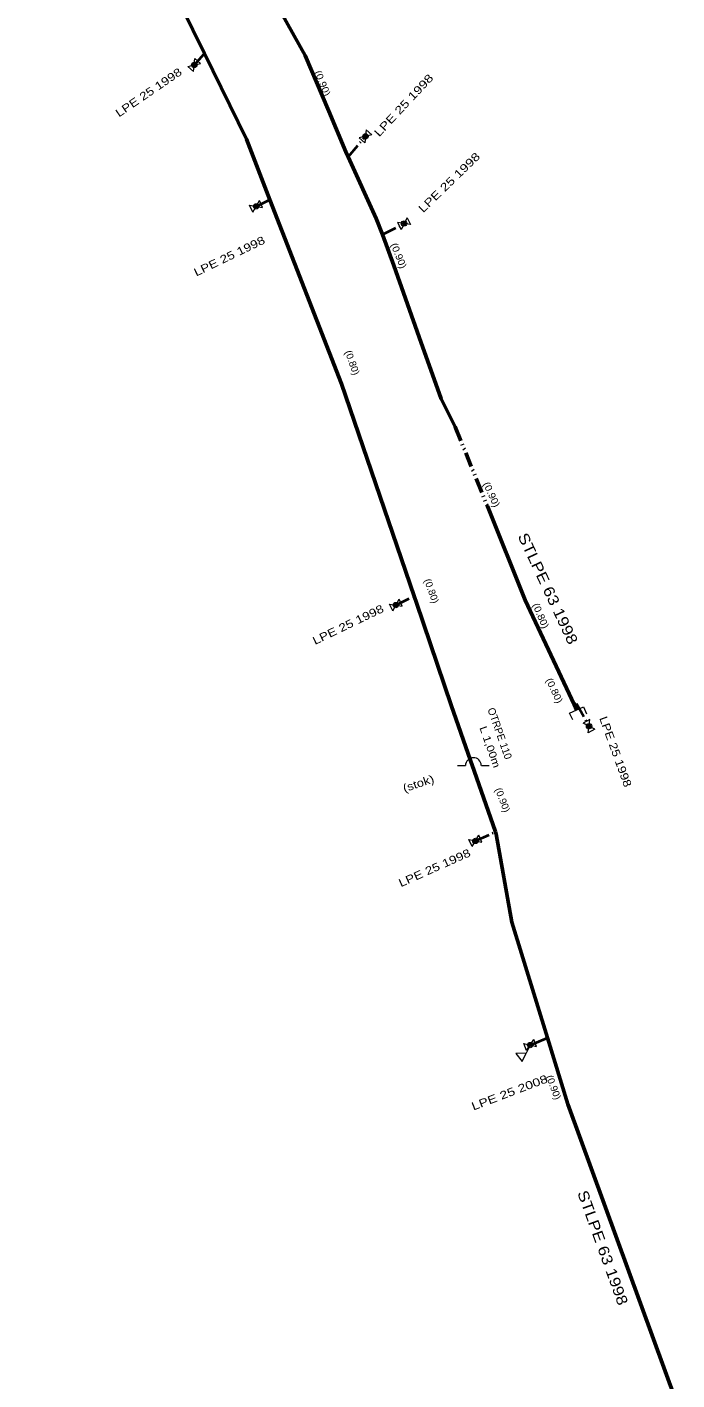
# Model space of a CAD drawing. Extents: x -648036 to -642998, y -1161549 to -1158141.
# Drawn here: x -646480.8 to -646420, y -1161219.3 to -1161092.5 of the extents above; entities that cross this region are included whole.
import ezdxf
from ezdxf.enums import TextEntityAlignment as Align

# ---------------------------------------------------------------- set-up
doc = ezdxf.new("R2010")
doc.units = 0
doc.header["$LTSCALE"] = 0.28
doc.linetypes.add('DASH_DOUBLE_DOT', pattern=[9.2, 5, -1.2, 0.3, -1.2, 0.3, -1.2])
for name, color, linetype, lineweight in [('12', 7, 'DASH_DOUBLE_DOT', 40), ('14', 7, 'Continuous', 13), ('15', 7, 'Continuous', 13), ('19', 7, 'Continuous', 13), ('8', 7, 'Continuous', 53)]:
    doc.layers.add(name, color=color, linetype=linetype, lineweight=lineweight)
for name, color, linetype in [('20', 7, 'Continuous'), ('22', 7, 'Continuous'), ('24', 7, 'Continuous'), ('27', 7, 'Continuous'), ('28', 7, 'Continuous')]:
    doc.layers.add(name, color=color, linetype=linetype)

msp = doc.modelspace()

# ---------------------------------------------------------------- linework, layer by layer
at = {"layer": '12'}
for p, q in [((-646465.2, -1161096.1), (-646464.24, -1161095.03)), ((-646450.79, -1161104.69), (-646449.16, -1161102.78)), ((-646459.4, -1161109.34), (-646458.11, -1161108.72)), ((-646447.58, -1161111.99), (-646445.55, -1161110.95)), ((-646446.32, -1161146.71), (-646444.6, -1161145.87)), ((-646438.87, -1161168.81), (-646436.99, -1161167.96))]:
    msp.add_line(p, q, dxfattribs=at)
at = {"layer": '12', "linetype": 'Continuous'}
msp.add_line((-646433.744, -1161187.942), (-646432.114, -1161187.278), dxfattribs=at)
at = {"layer": '12'}
msp.add_lwpolyline([(-646429.63, -1161156.03), (-646429.4, -1161155.93), (-646428.23, -1161158.06)], dxfattribs=at)
at = {"layer": '14'}
msp.add_line((-646438.99, -1161162.24), (-646439.32, -1161161.29), dxfattribs=at)
at = {"layer": '15'}
for p, q in [((-646465.272, -1161096.713), (-646465.128, -1161095.487)), ((-646464.599, -1161095.963), (-646465.128, -1161095.487)), ((-646465.802, -1161096.237), (-646464.599, -1161095.963)), ((-646465.272, -1161096.713), (-646465.802, -1161096.237)), ((-646448.562, -1161102.628), (-646449.757, -1161102.932)), ((-646449.757, -1161102.932), (-646449.216, -1161103.394)), ((-646449.104, -1161102.166), (-646449.216, -1161103.394)), ((-646449.104, -1161102.166), (-646448.562, -1161102.628)), ((-646460.008, -1161109.237), (-646458.792, -1161109.443)), ((-646459.7, -1161109.879), (-646460.008, -1161109.237)), ((-646459.7, -1161109.879), (-646459.1, -1161108.801)), ((-646458.792, -1161109.443), (-646459.1, -1161108.801)), ((-646445.264, -1161110.403), (-646445.836, -1161111.497)), ((-646445.264, -1161110.403), (-646444.939, -1161111.037)), ((-646446.16, -1161110.863), (-646445.836, -1161111.497)), ((-646444.939, -1161111.037), (-646446.16, -1161110.863)), ((-646446.617, -1161147.251), (-646446.023, -1161146.169)), ((-646445.712, -1161146.809), (-646446.023, -1161146.169)), ((-646446.929, -1161146.611), (-646445.712, -1161146.809)), ((-646446.617, -1161147.251), (-646446.929, -1161146.611)), ((-646428.16, -1161157.448), (-646428.785, -1161157.79)), ((-646428.299, -1161158.673), (-646428.16, -1161157.448)), ((-646427.675, -1161158.33), (-646428.785, -1161157.79)), ((-646427.675, -1161158.33), (-646428.299, -1161158.673)), ((-646440.535, -1161161.755), (-646439.8, -1161161.754)), ((-646438.314, -1161161.754), (-646437.58, -1161161.755)), ((-646439.476, -1161168.693), (-646438.265, -1161168.927)), ((-646439.183, -1161169.342), (-646439.476, -1161168.693)), ((-646439.183, -1161169.342), (-646438.557, -1161168.278)), ((-646438.265, -1161168.927), (-646438.557, -1161168.278)), ((-646434.345, -1161187.802), (-646433.144, -1161188.082)), ((-646434.076, -1161188.462), (-646434.345, -1161187.802)), ((-646433.744, -1161187.942), (-646434.12, -1161188.712)), ((-646434.076, -1161188.462), (-646433.412, -1161187.422)), ((-646433.144, -1161188.082), (-646433.412, -1161187.422))]:
    msp.add_line(p, q, dxfattribs=at)
msp.add_lwpolyline([(-646429.753, -1161157.473), (-646430.044, -1161156.83), (-646428.756, -1161156.25), (-646428.467, -1161156.892)], dxfattribs=at)
msp.add_lwpolyline([(-646434.12, -1161188.712), (-646435.081, -1161188.728), (-646434.501, -1161189.494)], close=True, dxfattribs=at)
msp.add_arc((-646439.0574, -1161161.7546), 0.7431, 1.2748, 179.83951, dxfattribs=at)
at = {"layer": '19'}
for centre, radius in [((-646465.2, -1161096.1), 0.25), ((-646465.2, -1161096.1), 0.17), ((-646465.2, -1161096.1), 0.09), ((-646449.16, -1161102.78), 0.25), ((-646449.16, -1161102.78), 0.17), ((-646449.16, -1161102.78), 0.09), ((-646459.4, -1161109.34), 0.25), ((-646459.4, -1161109.34), 0.17), ((-646459.4, -1161109.34), 0.09), ((-646445.55, -1161110.95), 0.25), ((-646445.55, -1161110.95), 0.17), ((-646445.55, -1161110.95), 0.09), ((-646446.32, -1161146.71), 0.25), ((-646446.32, -1161146.71), 0.17), ((-646446.32, -1161146.71), 0.09), ((-646428.23, -1161158.06), 0.25), ((-646428.23, -1161158.06), 0.17), ((-646428.23, -1161158.06), 0.09), ((-646438.87, -1161168.81), 0.25), ((-646438.87, -1161168.81), 0.17), ((-646438.87, -1161168.81), 0.09), ((-646433.744, -1161187.942), 0.25), ((-646433.744, -1161187.942), 0.17), ((-646433.744, -1161187.942), 0.09)]:
    msp.add_circle(centre, radius, dxfattribs=at)
at = {"layer": '8', "linetype": 'DASH_DOUBLE_DOT'}
msp.add_line((-646440.76, -1161130.02), (-646437.75, -1161137.44), dxfattribs=at)
at = {"layer": '8'}
for points in [[(-646480.85, -1161054.7), (-646480.75, -1161054.79), (-646479.19, -1161056.93), (-646475.49, -1161061.94), (-646470.89, -1161068.6), (-646468.7, -1161072.49), (-646463.29, -1161080.51), (-646459.4, -1161086.97), (-646454.82, -1161095.19), (-646452.58, -1161100.41), (-646450.99, -1161104.24), (-646450.79, -1161104.69)], [(-646464.24, -1161095.03), (-646466.41, -1161090.59), (-646470.76, -1161084.01)], [(-646458.11, -1161108.72), (-646460.31, -1161103.06), (-646464.24, -1161095.03)], [(-646450.79, -1161104.69), (-646448.15, -1161110.47), (-646447.58, -1161111.99)], [(-646444.6, -1161145.87), (-646451.4, -1161125.96), (-646458.11, -1161108.72)], [(-646447.58, -1161111.99), (-646446.5, -1161114.87), (-646444.12, -1161121.59), (-646442.06, -1161127.38), (-646440.76, -1161130.02)], [(-646437.75, -1161137.44), (-646434.21, -1161146.24), (-646429.63, -1161156.03), (-646429.4, -1161156.54)], [(-646436.99, -1161167.96), (-646438.99, -1161162.24), (-646439.32, -1161161.29), (-646441.13, -1161156.09), (-646444.38, -1161146.5), (-646444.6, -1161145.87)], [(-646432.114, -1161187.278), (-646435.46, -1161176.42), (-646436.91, -1161168.19), (-646436.99, -1161167.96)], [(-646420, -1161221.49), (-646430.2, -1161193.49), (-646432.114, -1161187.278)]]:
    msp.add_lwpolyline(points, dxfattribs=at)

# ---------------------------------------------------------------- texts
at = {"layer": '20', "width": 1.2}
for rotation, p in [(295.073, (-646432.5325, -1161145.3731)), (289.917, (-646427.415, -1161207.1067))]:
    msp.add_text('STLPE 63 1998', height=1, rotation=rotation, dxfattribs=at).set_placement(p, align=Align.CENTER)
at = {"layer": '22'}
for rotation, width, p in [(34.377, 1.25, (-646469.2557, -1161098.9715)), (46.983, 1.3, (-646445.3127, -1161100.1213)), (44.118, 1.3, (-646441.0616, -1161107.3735)), (25.783, 1.25, (-646461.7471, -1161114.3462)), (25.783, 1.25, (-646450.6271, -1161148.8762)), (289.917, 1.2, (-646426.0993, -1161160.5753)), (24.064, 1.25, (-646442.5404, -1161171.6781))]:
    msp.add_text('LPE 25 1998', height=0.75, rotation=rotation, dxfattribs=dict(at, width=width)).set_placement(p, align=Align.CENTER)
at = {"layer": '22', "width": 1.3}
msp.add_text('LPE 25 2008', height=0.75, rotation=20.847, dxfattribs=at).set_placement((-646439.059, -1161194.085))
at = {"layer": '24'}
msp.add_text('OTRPE 110', height=0.7, rotation=289.344, dxfattribs=at).set_placement((-646436.915, -1161158.8511), align=Align.CENTER)
at = {"layer": '24', "width": 1.2}
msp.add_text('L 1,00m', height=0.7, rotation=289.344, dxfattribs=at).set_placement((-646437.8312, -1161160.1176), align=Align.CENTER)
at = {"layer": '27'}
for s, rotation, width, p in [('(0.90)', 292.208, 1.1, (-646453.4796, -1161097.9257)), ('(0.90)', 292.208, 1.1, (-646446.3496, -1161114.0857)), ('(0.80)', 289.917, 1.05, (-646450.7009, -1161124.0963)), ('(0.90)', 294.5, 1.1, (-646437.6513, -1161136.4802)), ('(0.80)', 289.917, 1.05, (-646443.2809, -1161145.4963)), ('(0.80)', 293.354, 1.1, (-646433.0531, -1161147.8372)), ('(0.80)', 295.073, 1.1, (-646431.7676, -1161154.8573)), ('(0.90)', 291.063, 1.05, (-646436.6229, -1161165.0892)), ('(0.90)', 290.49, 1.05, (-646431.8446, -1161192.0157))]:
    msp.add_text(s, height=0.65, rotation=rotation, dxfattribs=dict(at, width=width)).set_placement(p, align=Align.CENTER)
at = {"layer": '28', "width": 1.2}
msp.add_text('(stok)', height=0.75, rotation=18.335, dxfattribs=at).set_placement((-646444.0875, -1161163.7866), align=Align.CENTER)

doc.saveas('drawing.dxf')
